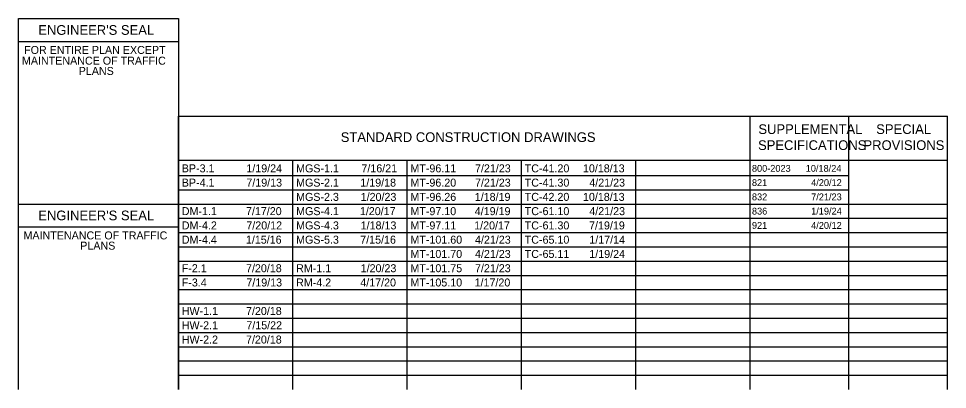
# Model space of a CAD drawing. Extents: x 0 to 34, y -32.5 to 22.
# Drawn here: x 2.1 to 18.35, y -32.53 to -26.03 of the extents above; entities that cross this region are included whole.
import ezdxf

# ---------------------------------------------------------------- set-up
doc = ezdxf.new("R2010")
doc.units = 0
doc.layers.add('GM_X_Adjacent_County', color=7, linetype='Continuous')
doc.layers.add('GM_X_Township', color=7, linetype='Continuous')

msp = doc.modelspace()

# ---------------------------------------------------------------- linework, layer by layer
at = {"layer": 'GM_X_Township'}
for p, q in [((2.1, -29.284), (2.1, -26.034)), ((2.1, -26.034), (4.9, -26.034)), ((4.9, -26.034), (4.9, -29.284)), ((2.1, -26.434), (4.9, -26.434)), ((4.9, -27.742), (18.35, -27.742)), ((4.9, -32.534), (4.9, -27.742)), ((14.9, -32.534), (14.9, -27.742)), ((16.625, -32.534), (16.625, -27.742)), ((18.35, -32.534), (18.35, -27.742)), ((4.9, -28.513), (18.35, -28.513)), ((6.9, -32.534), (6.9, -28.513)), ((8.9, -32.534), (8.9, -28.513)), ((10.9, -32.534), (10.9, -28.513)), ((12.9, -32.534), (12.9, -28.513)), ((4.9, -28.784), (16.625, -28.784)), ((4.9, -29.034), (16.625, -29.034)), ((2.1, -29.284), (4.9, -29.284)), ((2.1, -32.534), (2.1, -29.284)), ((4.9, -29.284), (18.35, -29.284)), ((4.9, -29.284), (4.9, -32.534)), ((4.9, -29.534), (18.35, -29.534)), ((2.1, -29.684), (4.9, -29.684)), ((4.9, -29.784), (18.35, -29.784)), ((4.9, -30.034), (18.35, -30.034)), ((4.9, -30.284), (18.35, -30.284)), ((4.9, -30.534), (18.35, -30.534)), ((4.9, -30.784), (18.35, -30.784)), ((4.9, -31.034), (18.35, -31.034)), ((4.9, -31.284), (18.35, -31.284)), ((4.9, -31.534), (18.35, -31.534)), ((4.9, -31.784), (18.35, -31.784)), ((4.9, -32.034), (18.35, -32.034)), ((4.9, -32.284), (18.35, -32.284))]:
    msp.add_line(p, q, dxfattribs=at)

# ---------------------------------------------------------------- texts
at = {"layer": 'GM_X_Adjacent_County'}
for s, height, p in [('SUPPLEMENTAL', 0.17, (15.043, -28.057)), ('SPECIAL', 0.17, (17.104, -28.057)), ('STANDARD CONSTRUCTION DRAWINGS', 0.17, (7.736, -28.197)), ('SPECIFICATIONS', 0.17, (15.037, -28.337)), ('PROVISIONS', 0.17, (16.882, -28.337)), ('BP-3.1', 0.14, (4.955, -28.729)), ('1/19/24', 0.14, (6.085, -28.729)), ('MGS-1.1', 0.14, (6.955, -28.729)), ('7/16/21', 0.14, (8.098, -28.729)), ('MT-96.11', 0.14, (8.955, -28.729)), ('7/21/23', 0.14, (10.085, -28.729)), ('TC-41.20', 0.14, (10.955, -28.729)), ('10/18/13', 0.14, (11.974, -28.729)), ('800-2023', 0.12, (14.93, -28.719)), ('10/18/24', 0.12, (15.871, -28.719)), ('BP-4.1', 0.14, (4.955, -28.979)), ('7/19/13', 0.14, (6.085, -28.979)), ('MGS-2.1', 0.14, (6.955, -28.979)), ('1/19/18', 0.14, (8.079, -28.979)), ('MT-96.20', 0.14, (8.955, -28.979)), ('7/21/23', 0.14, (10.085, -28.979)), ('TC-41.30', 0.14, (10.955, -28.979)), ('4/21/23', 0.14, (12.085, -28.979)), ('821', 0.12, (14.93, -28.969)), ('4/20/12', 0.12, (15.966, -28.969)), ('MGS-2.3', 0.14, (6.955, -29.229)), ('1/20/23', 0.14, (8.085, -29.229)), ('MT-96.26', 0.14, (8.955, -29.229)), ('1/18/19', 0.14, (10.081, -29.229)), ('TC-42.20', 0.14, (10.955, -29.229)), ('10/18/13', 0.14, (11.974, -29.229)), ('832', 0.12, (14.93, -29.219)), ('7/21/23', 0.12, (15.966, -29.219)), ('DM-1.1', 0.14, (4.955, -29.479)), ('7/17/20', 0.14, (6.078, -29.479)), ('MGS-4.1', 0.14, (6.955, -29.479)), ('1/20/17', 0.14, (8.071, -29.479)), ('MT-97.10', 0.14, (8.955, -29.479)), ('4/19/19', 0.14, (10.081, -29.479)), ('TC-61.10', 0.14, (10.955, -29.479)), ('4/21/23', 0.14, (12.085, -29.479)), ('836', 0.12, (14.93, -29.469)), ('1/19/24', 0.12, (15.966, -29.469)), ('DM-4.2', 0.14, (4.955, -29.729)), ('7/20/12', 0.14, (6.085, -29.729)), ('MGS-4.3', 0.14, (6.955, -29.729)), ('1/18/13', 0.14, (8.085, -29.729)), ('MT-97.11', 0.14, (8.955, -29.729)), ('1/20/17', 0.14, (10.071, -29.729)), ('TC-61.30', 0.14, (10.955, -29.729)), ('7/19/19', 0.14, (12.081, -29.729)), ('921', 0.12, (14.93, -29.719)), ('4/20/12', 0.12, (15.966, -29.719)), ('DM-4.4', 0.14, (4.955, -29.979)), ('1/15/16', 0.14, (6.077, -29.979)), ('MGS-5.3', 0.14, (6.955, -29.979)), ('7/15/16', 0.14, (8.077, -29.979)), ('MT-101.60', 0.14, (8.955, -29.979)), ('4/21/23', 0.14, (10.085, -29.979)), ('TC-65.10', 0.14, (10.955, -29.979)), ('1/17/14', 0.14, (12.085, -29.979)), ('MT-101.70', 0.14, (8.955, -30.229)), ('4/21/23', 0.14, (10.085, -30.229)), ('TC-65.11', 0.14, (10.955, -30.229)), ('1/19/24', 0.14, (12.085, -30.229)), ('F-2.1', 0.14, (4.955, -30.479)), ('7/20/18', 0.14, (6.079, -30.479)), ('RM-1.1', 0.14, (6.955, -30.479)), ('1/20/23', 0.14, (8.085, -30.479)), ('MT-101.75', 0.14, (8.955, -30.479)), ('7/21/23', 0.14, (10.085, -30.479)), ('F-3.4', 0.14, (4.955, -30.729)), ('7/19/13', 0.14, (6.085, -30.729)), ('RM-4.2', 0.14, (6.955, -30.729)), ('4/17/20', 0.14, (8.078, -30.729)), ('MT-105.10', 0.14, (8.955, -30.729)), ('1/17/20', 0.14, (10.078, -30.729)), ('HW-1.1', 0.14, (4.955, -31.229)), ('7/20/18', 0.14, (6.079, -31.229)), ('HW-2.1', 0.14, (4.955, -31.479)), ('7/15/22', 0.14, (6.085, -31.479)), ('HW-2.2', 0.14, (4.955, -31.729)), ('7/20/18', 0.14, (6.079, -31.729))]:
    msp.add_text(s, height=height, dxfattribs=at).set_placement(p)
at = {"layer": 'GM_X_Township'}
for s, height, p in [("ENGINEER'S SEAL", 0.17, (2.445, -26.319)), ('FOR ENTIRE PLAN EXCEPT', 0.14, (2.197, -26.654)), ('MAINTENANCE OF TRAFFIC', 0.14, (2.159, -26.842)), ('PLANS', 0.14, (3.152, -27.022)), ("ENGINEER'S SEAL", 0.17, (2.445, -29.569)), ('MAINTENANCE OF TRAFFIC', 0.14, (2.186, -29.904)), ('PLANS', 0.14, (3.179, -30.084))]:
    msp.add_text(s, height=height, dxfattribs=at).set_placement(p)

doc.saveas('drawing.dxf')
